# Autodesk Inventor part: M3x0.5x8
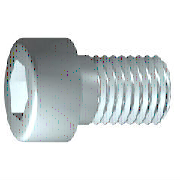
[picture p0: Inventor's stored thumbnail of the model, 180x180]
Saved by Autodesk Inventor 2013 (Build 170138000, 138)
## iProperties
IsCustomPart: 1
Company: 한국ATC센터
Created: 2009-02
Part Number: M3x0.5x8
Material: 강, 연강
Description: 6각머리 태핑 나사
Document SubType Name: Modeling
Standard: KS B 1003
Designer: KYOUNG IL JANG
Standards Organization: KS
Language: ko-KR
Size Designation: M 4 x 16
Categories: <MemberInstance><Categories><Category DisplayName="조임쇠" InternalName="e4da775c-781d-43d5-af7c-5136215cf5a6" Mnemonic="FSTN"><Category DisplayName="볼트" InternalN
Density: 7.86 g/cm^3
Mass: 2.43327 g
Surface Area: 3.56234 cm^2
Volume: 0.309576 cm^3
Vendor: CBT Solutions
Author: KYOUNG IL JANG
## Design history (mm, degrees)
sketch "스케치1"
  geometry: L1 (-1, 0)-(16, 0); L2 (16, 0)-(16, 2); L3 (16, 2)-(1.75, 2); L4 (1.75, 2)-(1.32, 2); L5 (1.32, 2)-(0, 2); L6 (0, 2)-(0, 3.5); L7 (0, 3.5)-(-4, 3.5); L8 (-4, 3.5)-(-4, 1.732); L9 (-4, 1.732)-(-2, 1.732); L10 (-2, 1.732)-(-1, 0); L11 (-8, 0)-(20, 0) reference; L12 (0, -0.7)-(0, 4.2) reference; L13 (1.75, 2)-(0, 2)
  constraints: 22 end point, 6 parallel, 2 collinear, 2 perpendicular, 1 horizontal, 1 point on line
  dimensions: "d1" = 14.25 distance from line of L3.end L2 (= GEL); "d2" = 0.42952 distance of L4.end L3.end (computed from GAL); "d3" = 4 distance between parallel lines of L8 L6 (= KOH); "d4" = 2 distance of L8.end L9.end (= INTI); "d5" = 60 deg angle of L10 L1; "d6" = 4 diameter of L3 L1 (= GD); "d7" = 4 diameter of L5 L1 (= BDM); "d8" = 3.4641 diameter of L9 L1 (= 1.1547 x SW); "d9" = 7 diameter of L7 L1 (= KOD); "d26" = 16 distance between parallel lines of L12 L2 (= NLG)
revolve "본체" sketch "스케치1" stored, may be unused: angle "d10" = 90 deg
sketch "스케치2"
  geometry: L1 (0, -4.9)-(0, 4.9) reference; L2 (-4.9, 0)-(4.9, 0) reference; L3 (1.732, 0)-(0.866, -1.5); L4 (0.866, -1.5)-(-0.866, -1.5); L5 (-0.866, -1.5)-(-1.732, 0); L6 (-1.732, 0)-(-0.866, 1.5); L7 (-0.866, 1.5)-(0.866, 1.5); L8 (0.866, 1.5)-(1.732, 0); 2 further points
  constraints: 12 end point, 1 coincident, 1 horizontal alignment, 1 point on line, 12 other
extrude "슬롯" join sketch "스케치2" stored distance "d11" = 10; taper "d12" = 0 deg
workplane "Work Plane1"
fillet "Fillet2" dims "d30" = 0.1 (= R)
sketch "스케치4"
  geometry: C1 r 2.574 at (0, 0); 1 further point
  constraints: 1 centre point, 1 coincident
extrude "돌출3" cut sketch "스케치4" distance "d31" = 2; taper "d32" = 0 deg
chamfer "모따기3" distance "d33" = 0.4; stored, may be unused: second distance "d34" = 2, angle "d35" = 45 deg
body "Solid1"
fillet "모깎기1" dims "d17" = 0.4 (= RR)
feature "스레드" dims "d13" = 14.25 (= GEL), "d14" = 0
chamfer "모따기1" distance "d15" = 0.42941 (= -0.5 x SPD + 0.5 x GD); stored, may be unused: second distance "d16" = 0.42941 (= GUL), angle "d27" = 45 deg
other parameters: "GD" = 4 (= NND) [user parameter; used in 2 equation terms], "NLG" = 16 [user parameter; used in 1 equation term], "GEL" = 14.25 [user parameter; used in 2 equation terms], "KOD" = 7 [user parameter; used in 1 equation term], "KOH" = 4 [user parameter; used in 1 equation term], "INTI" = 2 [user parameter; used in 1 equation term], "GAL" = 0.42941 (= 0.61345 x PTC) [user parameter; used in 1 equation term], "GUL" = 0.42941 (= 0.61345 x PTC) [user parameter; used in 1 equation term], "BDM" = 4 (= NND) [user parameter; used in 1 equation term], "SW" = 3 [user parameter; used in 2 equation terms], "RR" = 0.4 [user parameter; used in 1 equation term], "SPD" = 3.14117 (= NND - 1.2269 x PTC) [user parameter; used in 1 equation term], "d19" = 0, "d28" = 0, "d29" = 0, "R" = 0.1 [user parameter; used in 1 equation term], "PHH" = 0.2 [user parameter], "GD1" = 3.14117 (= THREADDIA - 1.2269 x PTC) [user parameter], "THREADDIA" = 4 [user parameter; used in 1 equation term], "FAWI" = 45 deg [user parameter], "TPU" = 14.28571 (computed from PTC) [user parameter], "PTC" = 0.7 [user parameter; used in 5 equation terms], "NND" = 4 [user parameter; used in 3 equation terms], "TOA" = 30 deg [user parameter], "E0" = 3.465 (= 1.155 x SW) [user parameter]
